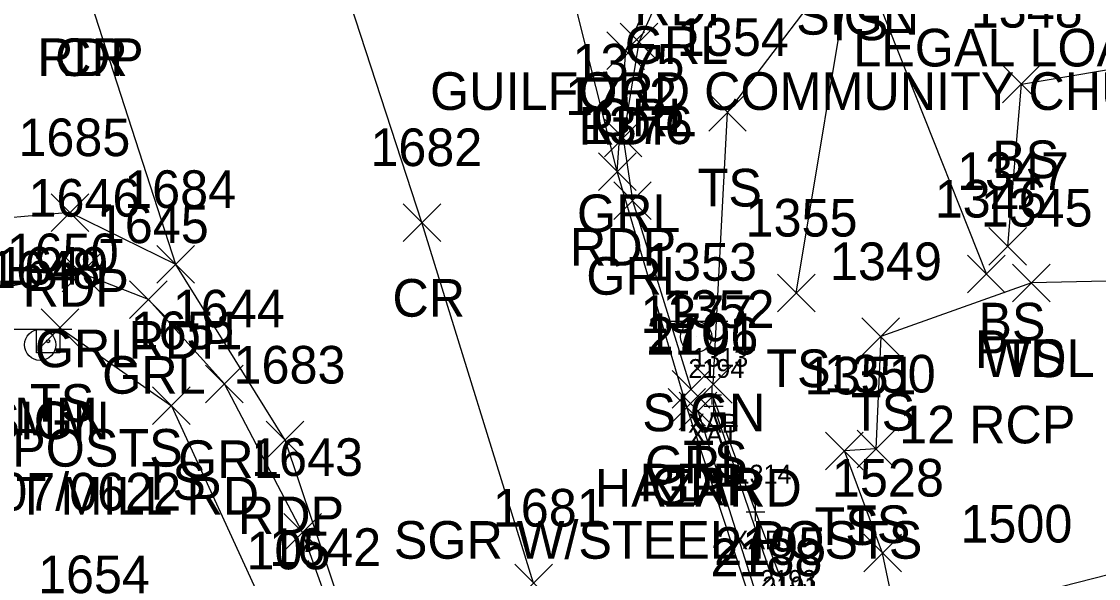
# Model space of a CAD drawing. Extents: x 1620157 to 1620595, y 115111 to 117885.
# Drawn here: x 1620300.9 to 1620358.1, y 115447.7 to 115477.3 of the extents above; entities that cross this region are included whole.
import ezdxf

# ---------------------------------------------------------------- set-up
doc = ezdxf.new("R2010")
doc.units = 0
for name, color, linetype in [('B_A', 7, 'Continuous'), ('B_I', 7, 'Continuous'), ('B_TIC', 7, 'Continuous'), ('BSUBM', 7, 'Continuous'), ('C_I', 7, 'Continuous'), ('D_A', 7, 'Continuous'), ('D_C', 7, 'Continuous'), ('D_I', 7, 'Continuous'), ('D_TIC', 7, 'Continuous'), ('DCP', 7, 'Continuous'), ('L_A', 7, 'Continuous'), ('L_I', 7, 'Continuous'), ('L_TIC', 7, 'Continuous'), ('LAWA', 7, 'Continuous'), ('LAWE', 7, 'Continuous'), ('LELB', 7, 'Continuous'), ('P_A', 7, 'Continuous'), ('P_I', 7, 'Continuous'), ('P_TIC', 7, 'Continuous'), ('PET', 7, 'Continuous'), ('PRC', 7, 'Continuous'), ('R_A', 7, 'Continuous'), ('R_C', 7, 'Continuous'), ('R_I', 7, 'Continuous'), ('R_TIC', 7, 'Continuous'), ('RGR', 7, 'Continuous'), ('S_A', 7, 'Continuous'), ('S_C', 7, 'Continuous'), ('S_I', 7, 'Continuous'), ('SRM', 7, 'Continuous'), ('SSGN', 7, 'Continuous')]:
    doc.layers.add(name, color=color, linetype=linetype)

msp = doc.modelspace()

# ---------------------------------------------------------------- linework, layer by layer
at = {"layer": 'B_TIC'}
for p, q in [((1620337.574, 115457.451), (1620337.65, 115457.451)), ((1620337.657, 115456.857), (1620337.732, 115456.857)), ((1620339.878, 115451.242), (1620339.954, 115451.242))]:
    msp.add_line(p, q, dxfattribs=at)
for points in [[(1620337.071, 115457.451), (1620338.071, 115457.451)], [(1620337.571, 115456.951), (1620337.571, 115457.951)], [(1620337.653, 115456.357), (1620337.653, 115457.357)], [(1620337.153, 115456.857), (1620338.153, 115456.857)], [(1620339.875, 115450.742), (1620339.875, 115451.742)], [(1620339.375, 115451.242), (1620340.375, 115451.242)]]:
    msp.add_lwpolyline(points, dxfattribs=at)
at = {"layer": 'BSUBM'}
for points in [[(1620337.571, 115457.451), (1620339.875, 115451.242), (1620343.416, 115441.84), (1620319.154, 115434.099), (1620315.832, 115433.966), (1620311.124, 115433.881), (1620309.777, 115434.975)], [(1620341.47, 115445.647), (1620337.653, 115456.857)]]:
    msp.add_lwpolyline(points, dxfattribs=at)
at = {"layer": 'D_TIC'}
for points in [[(1620351.145, 115462.878), (1620353.145, 115464.878)], [(1620353.145, 115462.878), (1620351.145, 115464.878)]]:
    msp.add_lwpolyline(points, dxfattribs=at)
at = {"layer": 'DCP'}
msp.add_lwpolyline([(1620352.145, 115463.878), (1620299.439, 115596.568)], dxfattribs=at)
at = {"layer": 'L_TIC'}
for points in [[(1620353.004, 115472.97), (1620355.004, 115474.97)], [(1620355.004, 115472.97), (1620353.004, 115474.97)], [(1620337.385, 115471.465), (1620339.385, 115473.465)], [(1620339.385, 115471.465), (1620337.385, 115473.465)], [(1620352.276, 115464.348), (1620354.276, 115466.348)], [(1620354.276, 115464.348), (1620352.276, 115466.348)], [(1620353.532, 115462.399), (1620355.532, 115464.399)], [(1620355.532, 115462.399), (1620353.532, 115464.399)], [(1620353.532, 115462.399), (1620355.532, 115464.399)], [(1620355.532, 115462.399), (1620353.532, 115464.399)], [(1620341.037, 115461.866), (1620343.037, 115463.866)], [(1620343.037, 115461.866), (1620341.037, 115463.866)], [(1620301.905, 115460.024), (1620303.905, 115462.024)], [(1620303.905, 115460.024), (1620301.905, 115462.024)], [(1620345.532, 115459.553), (1620347.532, 115461.553)], [(1620347.532, 115459.553), (1620345.532, 115461.553)], [(1620336.624, 115457.015), (1620338.624, 115459.015)], [(1620338.624, 115457.015), (1620336.624, 115459.015)], [(1620307.833, 115455.881), (1620309.833, 115457.881)], [(1620309.833, 115455.881), (1620307.833, 115457.881)], [(1620343.6, 115453.479), (1620345.6, 115455.479)], [(1620345.6, 115453.479), (1620343.6, 115455.479)], [(1620345.276, 115453.581), (1620347.276, 115455.581)], [(1620347.276, 115453.581), (1620345.276, 115455.581)], [(1620345.629, 115448.051), (1620347.629, 115450.051)], [(1620347.629, 115448.051), (1620345.629, 115450.051)]]:
    msp.add_lwpolyline(points, dxfattribs=at)
at = {"layer": 'LAWA'}
msp.add_lwpolyline([(1620457.22, 115455.235), (1620436.741, 115469.876), (1620415.841, 115471.908), (1620388.936, 115468.996), (1620365.7, 115463.66), (1620354.532, 115463.399)], dxfattribs=at)
at = {"layer": 'LAWE'}
msp.add_lwpolyline([(1620445.954, 115439.559), (1620430.826, 115447.795), (1620415.576, 115450.852), (1620397.572, 115447.406), (1620383.813, 115449.588), (1620366.252, 115449.835), (1620353.621, 115446.61), (1620348.794, 115438.684), (1620343.851, 115441.035)], dxfattribs=at)
at = {"layer": 'LELB'}
for points in [[(1620337.624, 115458.015), (1620338.385, 115472.465), (1620345.104, 115481.298), (1620360.593, 115485.956), (1620369.709, 115482.562), (1620378.951, 115489.571), (1620392.254, 115490.371), (1620442.829, 115488.336)], [(1620353.276, 115465.348), (1620354.004, 115473.97), (1620362.089, 115475.331), (1620372.56, 115475.834), (1620392.598, 115485.393), (1620443.084, 115483.249)], [(1620342.037, 115462.866), (1620345.104, 115481.298)], [(1620354.532, 115463.399), (1620346.532, 115460.553), (1620346.276, 115454.581), (1620344.6, 115454.479)], [(1620302.905, 115461.024), (1620308.833, 115456.881), (1620317.585, 115437.821)], [(1620346.629, 115449.051), (1620344.6, 115454.479)], [(1620348.794, 115438.684), (1620346.629, 115449.051)]]:
    msp.add_lwpolyline(points, dxfattribs=at)
at = {"layer": 'P_TIC'}
for points in [[(1620331.978, 115474.751), (1620333.978, 115476.751)], [(1620333.978, 115474.751), (1620331.978, 115476.751)], [(1620331.523, 115468.32), (1620333.523, 115470.32)], [(1620333.523, 115468.32), (1620331.523, 115470.32)], [(1620331.523, 115468.32), (1620333.523, 115470.32)], [(1620333.523, 115468.32), (1620331.523, 115470.32)], [(1620302.439, 115466.139), (1620304.439, 115468.139)], [(1620304.439, 115466.139), (1620302.439, 115468.139)], [(1620321.143, 115465.609), (1620323.143, 115467.609)], [(1620323.143, 115465.609), (1620321.143, 115467.609)], [(1620308.06, 115463.385), (1620310.06, 115465.385)], [(1620310.06, 115463.385), (1620308.06, 115465.385)], [(1620308.06, 115463.385), (1620310.06, 115465.385)], [(1620310.06, 115463.385), (1620308.06, 115465.385)], [(1620335.223, 115455.795), (1620337.223, 115457.795)], [(1620337.223, 115455.795), (1620335.223, 115457.795)], [(1620313.873, 115454.055), (1620315.873, 115456.055)], [(1620315.873, 115454.055), (1620313.873, 115456.055)], [(1620327.083, 115446.457), (1620329.083, 115448.457)], [(1620329.083, 115446.457), (1620327.083, 115448.457)]]:
    msp.add_lwpolyline(points, dxfattribs=at)
at = {"layer": 'PET'}
for points in [[(1620336.223, 115456.795), (1620332.523, 115469.32), (1620324.589, 115500.95), (1620318.089, 115527.231), (1620313.062, 115541.759), (1620309.737, 115554.427), (1620302.898, 115574.327), (1620297.627, 115590.435), (1620296.31, 115595.422), (1620295.446, 115598.549), (1620285.025, 115631.411), (1620284.003, 115634.579), (1620271.049, 115676.547), (1620263.941, 115701.458), (1620257.196, 115724.05), (1620247.856, 115755.871), (1620237.557, 115791.502), (1620229.867, 115820.365), (1620222.522, 115845.456)], [(1620320.138, 115439.395), (1620314.873, 115455.055), (1620309.06, 115464.385), (1620304.219, 115479.395), (1620297.094, 115496.088), (1620293.948, 115506.925), (1620292.02, 115512.471), (1620283.673, 115536.019), (1620274.577, 115564.814), (1620268.484, 115584.523), (1620253.11, 115635.23), (1620250.119, 115643.884), (1620242.654, 115668.014), (1620237.662, 115684.194), (1620235.083, 115693.763), (1620231.193, 115707.415), (1620225.409, 115727.426), (1620211.93, 115771.954), (1620203.83, 115799.038), (1620193.365, 115837.216)], [(1620332.523, 115469.32), (1620332.978, 115475.751), (1620335.945, 115482.085), (1620342.181, 115487.54), (1620351.662, 115490.258), (1620371.146, 115491.818), (1620394.104, 115493.245), (1620393.967, 115504.237), (1620393.248, 115515.154), (1620364.68, 115513.862), (1620340.552, 115513.335), (1620333.504, 115515.819), (1620326.046, 115520.006), (1620318.089, 115527.231)], [(1620309.06, 115464.385), (1620303.439, 115467.139), (1620297.793, 115466.657), (1620293.823, 115465.581), (1620290.733, 115473.222), (1620286.785, 115483.841), (1620293.207, 115489.941), (1620297.094, 115496.088)], [(1620340.172, 115444.819), (1620336.223, 115456.795)]]:
    msp.add_lwpolyline(points, dxfattribs=at)
at = {"layer": 'PRC'}
msp.add_lwpolyline([(1620328.083, 115447.457), (1620322.143, 115466.609), (1620311.316, 115499.812), (1620303.781, 115522.909), (1620294.725, 115551.741), (1620279.311, 115600.233), (1620271.119, 115626.45), (1620257.914, 115669.486), (1620247.637, 115703.034), (1620242.452, 115719.653), (1620232.976, 115752.347), (1620223.662, 115784.044), (1620214.136, 115816.154), (1620207.469, 115841.181)], dxfattribs=at)
at = {"layer": 'R_TIC'}
for points in [[(1620332.678, 115475.199), (1620334.678, 115477.199)], [(1620334.678, 115475.199), (1620332.678, 115477.199)], [(1620331.84, 115470.102), (1620333.84, 115472.102)], [(1620333.84, 115470.102), (1620331.84, 115472.102)], [(1620332.336, 115466.778), (1620334.336, 115468.778)], [(1620334.336, 115466.778), (1620332.336, 115468.778)], [(1620303.03, 115462.923), (1620305.03, 115464.923)], [(1620305.03, 115462.923), (1620303.03, 115464.923)], [(1620306.607, 115461.517), (1620308.607, 115463.517)], [(1620308.607, 115461.517), (1620306.607, 115463.517)], [(1620310.644, 115457.037), (1620312.644, 115459.037)], [(1620312.644, 115457.037), (1620310.644, 115459.037)], [(1620335.448, 115456.748), (1620337.448, 115458.748)], [(1620337.448, 115456.748), (1620335.448, 115458.748)], [(1620335.824, 115455.591), (1620337.824, 115457.591)], [(1620337.824, 115455.591), (1620335.824, 115457.591)], [(1620314.805, 115449.147), (1620316.805, 115451.147)], [(1620316.805, 115449.147), (1620314.805, 115451.147)]]:
    msp.add_lwpolyline(points, dxfattribs=at)
at = {"layer": 'RGR'}
for points in [[(1620369.42, 115483.557), (1620366.122, 115487.995), (1620361.68, 115489.414), (1620344.795, 115486.882), (1620339.22, 115484.245), (1620335.382, 115480.036), (1620333.678, 115476.199), (1620332.84, 115471.102), (1620333.336, 115467.778), (1620336.448, 115457.748)], [(1620319.469, 115439.936), (1620315.805, 115450.147), (1620311.644, 115458.037), (1620307.607, 115462.517), (1620304.03, 115463.923), (1620297.139, 115462.641)], [(1620340.366, 115445.424), (1620336.824, 115456.591)]]:
    msp.add_lwpolyline(points, dxfattribs=at)
at = {"layer": 'SRM'}
msp.add_lwpolyline([(1620301.657, 115460.936), (1620302.907, 115460.936), (1620302.907, 115459.686), (1620301.657, 115459.686)], close=True, dxfattribs=at)
msp.add_circle((1620302.282, 115460.311), 0.0833, dxfattribs=at)
at = {"layer": 'SSGN'}
for p, q in [((1620300.207, 115460.95), (1620303.541, 115460.95)), ((1620335.071, 115461.374), (1620338.404, 115461.374)), ((1620336.717, 115460.54), (1620336.717, 115460.54)), ((1620301.854, 115460.116), (1620301.854, 115460.116))]:
    msp.add_line(p, q, dxfattribs=at)
for centre in [(1620301.854, 115460.116), (1620336.717, 115460.54)]:
    msp.add_circle(centre, 0.833, dxfattribs=at)

# ---------------------------------------------------------------- texts
at = {"layer": 'B_A'}
for s, p in [('XAB', (1620336.291, 115455.451)), ('XAT', (1620336.358, 115454.857)), ('XAB', (1620338.595, 115449.242))]:
    msp.add_text(s, height=1, dxfattribs=at).set_placement(p)
at = {"layer": 'B_I'}
for s, p in [('1313', (1620336.508, 115458.951)), ('2194', (1620336.307, 115458.357)), ('1314', (1620338.812, 115452.742)), ('2193', (1620340.124, 115447.147)), ('2191', (1620340.231, 115446.797))]:
    msp.add_text(s, height=1, dxfattribs=at).set_placement(p)
at = {"layer": 'C_I'}
msp.add_text('105', height=2, dxfattribs=at).set_placement((1620312.819, 115448.184))
at = {"layer": 'D_A'}
msp.add_text('P', height=2, dxfattribs=at).set_placement((1620351.523, 115458.878))
at = {"layer": 'D_C'}
msp.add_text('12 RCP', height=2, dxfattribs=at).set_placement((1620347.508, 115454.878))
at = {"layer": 'D_I'}
msp.add_text('1346', height=2, dxfattribs=at).set_placement((1620349.397, 115466.878))
at = {"layer": 'L_A'}
for s, p in [('TS', (1620343.513, 115476.298)), ('TS', (1620343.513, 115476.298)), ('BS', (1620352.445, 115468.97)), ('TS', (1620336.795, 115467.465)), ('BS', (1620351.717, 115460.348)), ('WDL', (1620351.949, 115458.399)), ('TS', (1620352.941, 115458.399)), ('TS', (1620340.447, 115457.866)), ('TS', (1620301.315, 115456.024)), ('TS', (1620344.941, 115455.553)), ('TS', (1620336.034, 115453.015)), ('TS', (1620307.243, 115451.881)), ('TS', (1620343.01, 115449.479)), ('TS', (1620344.686, 115449.581))]:
    msp.add_text(s, height=2, dxfattribs=at).set_placement(p)
at = {"layer": 'L_I'}
for s, p in [('1348', (1620351.311, 115476.97)), ('1354', (1620335.693, 115475.465)), ('1347', (1620350.583, 115468.348)), ('1345', (1620351.839, 115466.399)), ('1345', (1620351.839, 115466.399)), ('1355', (1620339.345, 115465.866)), ('1650', (1620300.078, 115464.024)), ('1349', (1620343.831, 115463.553)), ('1352', (1620334.932, 115461.015)), ('1651', (1620306.66, 115459.881)), ('1351', (1620342.475, 115457.479)), ('1350', (1620343.497, 115457.581)), ('1528', (1620343.936, 115452.051)), ('1500', (1620350.763, 115449.61)), ('1500', (1620350.763, 115449.61)), ('1654', (1620301.742, 115446.918))]:
    msp.add_text(s, height=2, dxfattribs=at).set_placement(p)
at = {"layer": 'P_A'}
for s, p in [('RDP', (1620333.433, 115477.085)), ('RDP', (1620301.707, 115474.395)), ('CR', (1620302.652, 115474.395)), ('RDP', (1620330.467, 115470.751)), ('RDP', (1620330.012, 115464.32)), ('RDP', (1620330.012, 115464.32)), ('RDP', (1620300.927, 115462.139)), ('CR', (1620320.576, 115461.609)), ('RDP', (1620306.548, 115459.385)), ('RDP', (1620306.548, 115459.385)), ('RDP', (1620333.711, 115451.795)), ('RDP', (1620312.361, 115450.055))]:
    msp.add_text(s, height=2, dxfattribs=at).set_placement(p)
at = {"layer": 'P_I'}
for s, p in [('1702', (1620329.752, 115472.32)), ('1702', (1620329.752, 115472.32)), ('1685', (1620300.699, 115470.139)), ('1682', (1620319.403, 115469.609)), ('1684', (1620306.32, 115467.385)), ('1684', (1620306.32, 115467.385)), ('1701', (1620334.018, 115459.795)), ('1683', (1620312.133, 115458.055)), ('1681', (1620325.91, 115450.457)), ('2188', (1620337.48, 115447.819))]:
    msp.add_text(s, height=2, dxfattribs=at).set_placement(p)
at = {"layer": 'R_A'}
for s, p in [('GRL', (1620332.925, 115475.036)), ('GRL', (1620331.221, 115471.199)), ('GRL', (1620330.383, 115466.102)), ('GRL', (1620330.879, 115462.778)), ('GRL', (1620301.573, 115458.923)), ('GRL', (1620305.15, 115457.517)), ('GRL', (1620309.187, 115453.037)), ('GRL', (1620333.991, 115452.748)), ('GRR', (1620334.312, 115451.591))]:
    msp.add_text(s, height=2, dxfattribs=at).set_placement(p)
at = {"layer": 'R_C'}
for p in [(1620281.344, 115453.641), (1620320.653, 115448.748)]:
    msp.add_text('SGR W/STEEL POSTS', height=2, dxfattribs=at).set_placement(p)
at = {"layer": 'R_I'}
for s, p in [('1375', (1620330.147, 115474.102)), ('1376', (1620330.588, 115470.778)), ('1646', (1620301.235, 115466.923)), ('1645', (1620304.867, 115465.517)), ('1644', (1620308.904, 115461.037)), ('1377', (1620333.755, 115460.748)), ('2196', (1620334.076, 115459.591)), ('1643', (1620313.065, 115453.147)), ('2195', (1620337.673, 115448.424))]:
    msp.add_text(s, height=2, dxfattribs=at).set_placement(p)
at = {"layer": 'S_A'}
for s, p in [('SIGN', (1620342.035, 115476.594)), ('SIGN', (1620333.856, 115455.52)), ('SIGN', (1620298.992, 115455.096)), ('MM', (1620300.471, 115455.311))]:
    msp.add_text(s, height=2, dxfattribs=at).set_placement(p)
at = {"layer": 'S_C'}
for s, p in [('LEGAL LOAD LIMIT 24000 POUNDS', (1620345.066, 115474.903)), ('GUILFORD COMMUNITY CHURCH', (1620322.578, 115472.594)), ('HAZARD', (1620331.336, 115451.52)), ('STOP/ GRIST MILL RD', (1620285.26, 115451.096)), ('0050/1307/0622', (1620290.015, 115451.311))]:
    msp.add_text(s, height=2, dxfattribs=at).set_placement(p)
at = {"layer": 'S_I'}
for s, p in [('1353', (1620334.005, 115463.52)), ('1648', (1620299.095, 115463.096)), ('1649', (1620299.534, 115463.311)), ('1642', (1620314.029, 115448.366))]:
    msp.add_text(s, height=2, dxfattribs=at).set_placement(p)

doc.saveas('drawing.dxf')
